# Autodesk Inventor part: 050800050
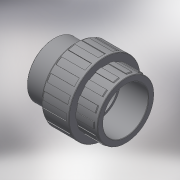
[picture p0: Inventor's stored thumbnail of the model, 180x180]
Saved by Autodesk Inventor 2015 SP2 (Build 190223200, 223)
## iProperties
Created: 2017-10
Part Number: 050800050
Material: Generic
Description: PLASSON UNION+O RING-CEM PVC 50
Document SubType Name: Modeling
Designer: Кирилл
Density: 1 g/cm^3
Appearance: Default
Author: Кирилл
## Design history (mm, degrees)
derived "050800.ipt"
feature "Solid1::050800.ipt"
tag "TaggingFeature1"
body "Solid1"
other parameters: "d0" = 79, "d6" = 62.5, "d7" = 64, "d8" = 79, "d9" = 31, "d10" = 31, "d11" = 45, "d12" = 47.5, "d14" = 23.25, "d15" = 23.25, "d16" = 15.3, "d17" = 3.1, "d19" = 77.42, "d20" = 3.1, "d21" = 2.37, "d25" = 7.9, "d26" = 3.95, "d27" = 26.46, "d28" = 0, "d32" = 7.9, "d33" = 3.95, "d35" = 0, "d39" = 0.5, "d45" = 0.75, "d49" = 360 deg, "d51" = 0.79, "d55" = 360 deg, "E_" = 79, "H_" = 79, "l_" = 31, "l_1" = 31, "Z_" = 17, "d13" = 17, "d24" = 29.4, "d40" = 0.75, "d44" = 0.79
